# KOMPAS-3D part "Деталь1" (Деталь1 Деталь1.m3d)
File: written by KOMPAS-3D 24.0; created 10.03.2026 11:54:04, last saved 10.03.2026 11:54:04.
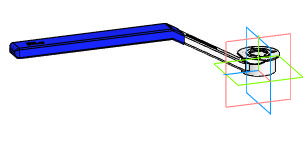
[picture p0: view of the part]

Document properties: Автор: R2D2; Полное имя файла: E:\Работа\Зайцев\BV3232P(4pc)-FP-3WL-F-ISO-H Кран шаровой DN.ru Ду15-100 Ру16\DN20\исходные материалы\Деталь1 Деталь1.m3d

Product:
- Body: Твердое тело1  | qty 1
- Part/product: Деталь1
    additional columns: Типовые

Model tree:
1. Твердое тело1  (labels: Твердое тело1)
